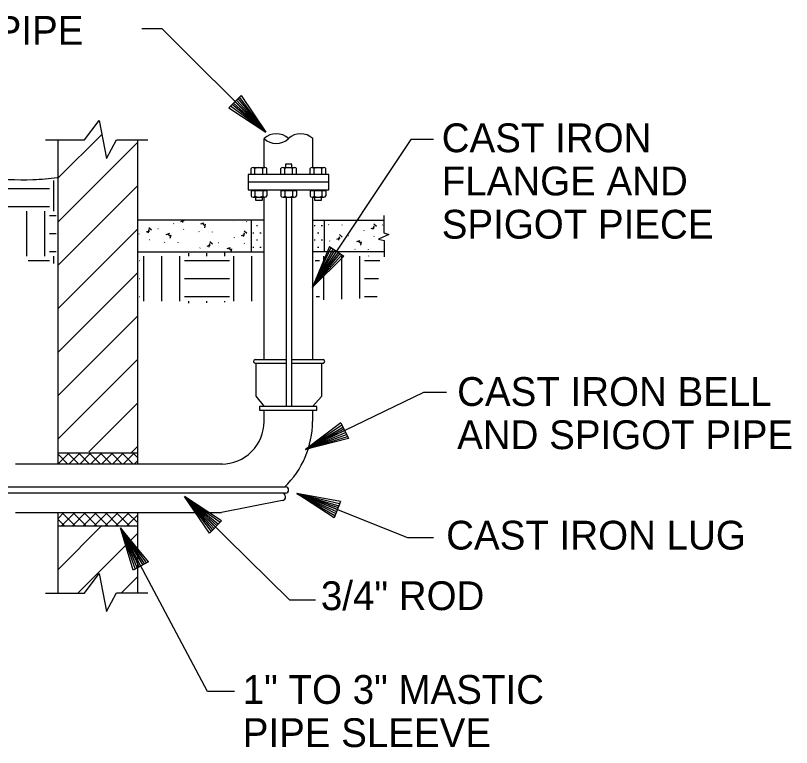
# Model space of a CAD drawing. Extents: x 9999.96 to 10005.26, y 9999.88 to 10002.38.
# Drawn here: x 10001.3058 to 10001.5752, y 10001.9706 to 10002.2247 of the extents above; entities that cross this region are included whole.
import ezdxf

# ---------------------------------------------------------------- set-up
doc = ezdxf.new("R2010")
doc.units = 0
doc.layers.add('Level 2', color=7, linetype='Continuous')

msp = doc.modelspace()

# ---------------------------------------------------------------- linework, layer by layer
at = {"layer": 'Level 2'}
for p, q in [((10001.379875, 10002.192729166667), (10001.384145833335, 10002.196989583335)), ((10001.392645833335, 10002.184208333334), (10001.382520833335, 10002.195375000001)), ((10001.392645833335, 10002.184208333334), (10001.383041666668, 10002.195906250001)), ((10001.392645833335, 10002.184208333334), (10001.383562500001, 10002.196416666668)), ((10001.384145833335, 10002.196989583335), (10001.392645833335, 10002.184208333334)), ((10001.379875, 10002.192729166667), (10001.392645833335, 10002.184208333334)), ((10001.392645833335, 10002.184208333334), (10001.380416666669, 10002.193270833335)), ((10001.392645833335, 10002.184208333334), (10001.381000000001, 10002.193885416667)), ((10001.392645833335, 10002.184208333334), (10001.381489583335, 10002.194343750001)), ((10001.381979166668, 10002.194843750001), (10001.392645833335, 10002.184208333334)), ((10001.320645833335, 10002.168333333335), (10001.335781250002, 10002.183468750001)), ((10001.392083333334, 10002.172010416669), (10001.392083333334, 10002.182)), ((10001.408885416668, 10002.182), (10001.408885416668, 10002.172010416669)), ((10001.320645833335, 10002.069031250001), (10001.320645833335, 10002.181541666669)), ((10001.320656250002, 10002.153250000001), (10001.348083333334, 10002.180687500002)), ((10001.348083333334, 10002.181541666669), (10001.348083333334, 10002.069031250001)), ((10001.387562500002, 10002.169677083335), (10001.387562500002, 10002.171583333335)), ((10001.388250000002, 10002.172010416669), (10001.392354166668, 10002.172010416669)), ((10001.388927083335, 10002.169677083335), (10001.388927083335, 10002.171583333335)), ((10001.391677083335, 10002.169677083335), (10001.391677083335, 10002.171583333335)), ((10001.393041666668, 10002.169677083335), (10001.393041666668, 10002.171572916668)), ((10001.397875, 10002.169677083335), (10001.397875, 10002.171583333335)), ((10001.3985625, 10002.172010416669), (10001.402666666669, 10002.172010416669)), ((10001.399239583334, 10002.169677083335), (10001.399239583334, 10002.171583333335)), ((10001.401989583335, 10002.169677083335), (10001.401989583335, 10002.171583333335)), ((10001.403354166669, 10002.169677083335), (10001.403354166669, 10002.171572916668)), ((10001.4080625, 10002.169677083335), (10001.4080625, 10002.171583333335)), ((10001.40875, 10002.172010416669), (10001.412854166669, 10002.172010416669)), ((10001.409427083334, 10002.169677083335), (10001.409427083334, 10002.171583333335)), ((10001.412177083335, 10002.169677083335), (10001.412177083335, 10002.171583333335)), ((10001.413541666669, 10002.169677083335), (10001.413541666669, 10002.171572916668)), ((10001.387562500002, 10002.169677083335), (10001.393041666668, 10002.169677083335)), ((10001.397875, 10002.169677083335), (10001.403354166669, 10002.169677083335)), ((10001.4080625, 10002.169677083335), (10001.413541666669, 10002.169677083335)), ((10001.319104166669, 10002.156843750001), (10001.319104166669, 10002.167500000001)), ((10001.320656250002, 10002.138166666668), (10001.348083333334, 10002.165604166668)), ((10001.414593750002, 10002.166833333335), (10001.386552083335, 10002.166833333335)), ((10001.301916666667, 10002.164656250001), (10001.317541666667, 10002.164656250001)), ((10001.387562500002, 10002.163989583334), (10001.393041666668, 10002.163989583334)), ((10001.387562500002, 10002.163989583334), (10001.387562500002, 10002.162083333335)), ((10001.388927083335, 10002.163989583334), (10001.388927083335, 10002.162083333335)), ((10001.391677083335, 10002.163989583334), (10001.391677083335, 10002.162083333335)), ((10001.393041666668, 10002.163989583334), (10001.393041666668, 10002.162093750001)), ((10001.397875, 10002.163989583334), (10001.403354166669, 10002.163989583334)), ((10001.397875, 10002.163989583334), (10001.397875, 10002.162083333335)), ((10001.399239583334, 10002.163989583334), (10001.399239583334, 10002.162083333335)), ((10001.401989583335, 10002.163989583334), (10001.401989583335, 10002.162083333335)), ((10001.403354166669, 10002.163989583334), (10001.403354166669, 10002.162093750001)), ((10001.4080625, 10002.163989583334), (10001.413541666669, 10002.163989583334)), ((10001.4080625, 10002.163989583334), (10001.4080625, 10002.162083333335)), ((10001.409427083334, 10002.163989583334), (10001.409427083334, 10002.162083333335)), ((10001.412177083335, 10002.163989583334), (10001.412177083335, 10002.162083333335)), ((10001.413541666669, 10002.163989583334), (10001.413541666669, 10002.162093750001)), ((10001.388250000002, 10002.161656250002), (10001.392354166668, 10002.161656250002)), ((10001.392083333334, 10002.105260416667), (10001.392083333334, 10002.161718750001)), ((10001.3985625, 10002.161656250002), (10001.402666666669, 10002.161656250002)), ((10001.39975, 10002.161656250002), (10001.39975, 10002.089010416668)), ((10001.401718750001, 10002.089010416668), (10001.401718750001, 10002.161656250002)), ((10001.40875, 10002.161656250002), (10001.412854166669, 10002.161656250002)), ((10001.408885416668, 10002.161656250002), (10001.408885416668, 10002.105260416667)), ((10001.301916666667, 10002.15840625), (10001.317541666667, 10002.15840625)), ((10001.309729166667, 10002.141218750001), (10001.309729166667, 10002.156843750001)), ((10001.315979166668, 10002.141218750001), (10001.315979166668, 10002.156843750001)), ((10001.317541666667, 10002.155281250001), (10001.319916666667, 10002.155281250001)), ((10001.392083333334, 10002.153645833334), (10001.348083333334, 10002.153645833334)), ((10001.360677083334, 10002.15246875), (10001.360697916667, 10002.152572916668)), ((10001.363156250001, 10002.153239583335), (10001.364354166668, 10002.153604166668)), ((10001.363916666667, 10002.153645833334), (10001.363729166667, 10002.152833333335)), ((10001.371177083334, 10002.152666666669), (10001.369979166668, 10002.152302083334)), ((10001.370614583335, 10002.152593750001), (10001.371520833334, 10002.15175)), ((10001.371468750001, 10002.151052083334), (10001.371750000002, 10002.152270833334)), ((10001.381510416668, 10002.153291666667), (10001.381437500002, 10002.153364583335)), ((10001.386052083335, 10002.153239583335), (10001.386031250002, 10002.153135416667)), ((10001.387645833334, 10002.153614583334), (10001.387645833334, 10002.142677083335)), ((10001.408885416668, 10002.153645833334), (10001.433614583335, 10002.153645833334)), ((10001.413, 10002.153645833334), (10001.413, 10002.142677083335)), ((10001.414572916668, 10002.15209375), (10001.4145, 10002.152156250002)), ((10001.416500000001, 10002.153479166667), (10001.416552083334, 10002.153697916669)), ((10001.431104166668, 10002.151489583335), (10001.430187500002, 10002.152343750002)), ((10001.320656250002, 10002.12309375), (10001.348083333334, 10002.150520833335)), ((10001.351208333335, 10002.149583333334), (10001.352395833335, 10002.149947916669)), ((10001.352041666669, 10002.150395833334), (10001.351760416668, 10002.149187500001)), ((10001.353020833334, 10002.150239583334), (10001.352114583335, 10002.151083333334)), ((10001.355187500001, 10002.150802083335), (10001.355312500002, 10002.150833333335)), ((10001.364197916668, 10002.150531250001), (10001.364104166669, 10002.150500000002)), ((10001.369552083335, 10002.149635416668), (10001.369479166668, 10002.149708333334)), ((10001.37409375, 10002.149583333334), (10001.374072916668, 10002.149489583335)), ((10001.386083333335, 10002.149031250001), (10001.385166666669, 10002.149885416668)), ((10001.389416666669, 10002.151843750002), (10001.389833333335, 10002.151843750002)), ((10001.391916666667, 10002.151843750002), (10001.3919375, 10002.151843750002)), ((10001.409427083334, 10002.151843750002), (10001.409833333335, 10002.151843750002)), ((10001.411916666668, 10002.151843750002), (10001.412343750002, 10002.151843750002)), ((10001.419125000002, 10002.152020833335), (10001.419104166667, 10002.151916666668)), ((10001.426822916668, 10002.150031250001), (10001.426843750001, 10002.150125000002)), ((10001.429260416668, 10002.150791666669), (10001.430458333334, 10002.151156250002)), ((10001.43015625, 10002.151614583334), (10001.429875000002, 10002.150395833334)), ((10001.433250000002, 10002.152010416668), (10001.433364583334, 10002.152041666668)), ((10001.317541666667, 10002.149031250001), (10001.319916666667, 10002.149031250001)), ((10001.348718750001, 10002.148822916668), (10001.348739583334, 10002.148916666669)), ((10001.352250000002, 10002.146875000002), (10001.352145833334, 10002.14684375)), ((10001.359218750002, 10002.149010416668), (10001.358020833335, 10002.148645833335)), ((10001.35865625, 10002.148937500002), (10001.359562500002, 10002.148083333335)), ((10001.359510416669, 10002.147395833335), (10001.359791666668, 10002.148614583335)), ((10001.381791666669, 10002.147593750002), (10001.381812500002, 10002.147697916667)), ((10001.384260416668, 10002.148354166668), (10001.385447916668, 10002.14871875)), ((10001.385114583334, 10002.149177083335), (10001.384833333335, 10002.147958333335)), ((10001.388166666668, 10002.149343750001), (10001.388583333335, 10002.149343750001)), ((10001.389416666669, 10002.14684375), (10001.389833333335, 10002.14684375)), ((10001.390666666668, 10002.149343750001), (10001.391083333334, 10002.149343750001)), ((10001.391916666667, 10002.14684375), (10001.391947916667, 10002.14684375)), ((10001.409427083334, 10002.14684375), (10001.409833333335, 10002.14684375)), ((10001.410666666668, 10002.149343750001), (10001.411083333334, 10002.149343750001)), ((10001.411916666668, 10002.14684375), (10001.412343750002, 10002.14684375)), ((10001.417312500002, 10002.147135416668), (10001.418500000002, 10002.147500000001)), ((10001.418187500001, 10002.147958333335), (10001.41790625, 10002.146739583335)), ((10001.419145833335, 10002.147822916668), (10001.418229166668, 10002.148677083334)), ((10001.421291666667, 10002.148354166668), (10001.421416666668, 10002.148385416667)), ((10001.430302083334, 10002.148083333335), (10001.430208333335, 10002.148052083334)), ((10001.35759375, 10002.145968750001), (10001.357520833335, 10002.146041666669)), ((10001.362135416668, 10002.145937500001), (10001.362114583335, 10002.145833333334)), ((10001.369822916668, 10002.143947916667), (10001.369854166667, 10002.144041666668)), ((10001.372302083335, 10002.144697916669), (10001.373500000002, 10002.145072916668)), ((10001.373156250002, 10002.145531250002), (10001.372875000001, 10002.1443125)), ((10001.374125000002, 10002.145375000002), (10001.373208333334, 10002.146218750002)), ((10001.37628125, 10002.145916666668), (10001.376406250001, 10002.145958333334)), ((10001.380322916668, 10002.144135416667), (10001.379125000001, 10002.143770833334)), ((10001.379750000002, 10002.144072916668), (10001.380666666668, 10002.143218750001)), ((10001.385302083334, 10002.14565625), (10001.385197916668, 10002.145625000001)), ((10001.388166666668, 10002.144343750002), (10001.388583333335, 10002.144343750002)), ((10001.390666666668, 10002.144343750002), (10001.391083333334, 10002.144343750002)), ((10001.414770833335, 10002.144583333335), (10001.408947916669, 10002.130375)), ((10001.408947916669, 10002.130375), (10001.415406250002, 10002.144156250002)), ((10001.410666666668, 10002.144343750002), (10001.411083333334, 10002.144343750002)), ((10001.414770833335, 10002.144583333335), (10001.41978125, 10002.141239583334)), ((10001.414864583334, 10002.146375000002), (10001.414885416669, 10002.146479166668)), ((10001.418354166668, 10002.144437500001), (10001.41825, 10002.144406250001)), ((10001.425322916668, 10002.146562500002), (10001.424125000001, 10002.146197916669)), ((10001.424770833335, 10002.14653125), (10001.425687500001, 10002.145677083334)), ((10001.425656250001, 10002.144958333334), (10001.425937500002, 10002.146166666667)), ((10001.317541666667, 10002.14278125), (10001.319916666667, 10002.14278125)), ((10001.348083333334, 10002.142666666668), (10001.392083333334, 10002.142666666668)), ((10001.365979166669, 10002.141218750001), (10001.365979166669, 10002.142187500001)), ((10001.372229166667, 10002.141218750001), (10001.372229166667, 10002.142239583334)), ((10001.378479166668, 10002.141218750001), (10001.378479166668, 10002.142291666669)), ((10001.380635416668, 10002.14259375), (10001.380895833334, 10002.143739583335)), ((10001.433614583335, 10002.142666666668), (10001.408885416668, 10002.142666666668)), ((10001.408947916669, 10002.130375), (10001.416125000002, 10002.143708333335)), ((10001.408947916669, 10002.130375), (10001.416666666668, 10002.143322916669)), ((10001.417260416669, 10002.1429375), (10001.408947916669, 10002.130375)), ((10001.408947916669, 10002.130375), (10001.417885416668, 10002.142510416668)), ((10001.408947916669, 10002.130375), (10001.418510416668, 10002.142114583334)), ((10001.408947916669, 10002.130375), (10001.419104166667, 10002.141697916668)), ((10001.423718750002, 10002.143562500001), (10001.423645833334, 10002.143635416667)), ((10001.42828125, 10002.143489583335), (10001.428260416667, 10002.143385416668)), ((10001.428479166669, 10002.141218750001), (10001.428479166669, 10002.141322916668)), ((10001.310208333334, 10002.139656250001), (10001.317541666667, 10002.139656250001)), ((10001.319104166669, 10002.138666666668), (10001.319104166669, 10002.141218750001)), ((10001.348708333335, 10002.139656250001), (10001.348791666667, 10002.139656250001)), ((10001.350354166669, 10002.125593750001), (10001.350354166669, 10002.141218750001)), ((10001.356604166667, 10002.125593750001), (10001.356604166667, 10002.141218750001)), ((10001.362854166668, 10002.125593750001), (10001.362854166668, 10002.141218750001)), ((10001.364416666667, 10002.139656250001), (10001.380041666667, 10002.139656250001)), ((10001.381604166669, 10002.125593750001), (10001.381604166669, 10002.141218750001)), ((10001.387854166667, 10002.125593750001), (10001.387854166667, 10002.141218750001)), ((10001.41978125, 10002.141239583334), (10001.408947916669, 10002.130375)), ((10001.409802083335, 10002.139656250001), (10001.411291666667, 10002.139656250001)), ((10001.412854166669, 10002.126000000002), (10001.412854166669, 10002.141218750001)), ((10001.419104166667, 10002.126229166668), (10001.419104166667, 10002.141218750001)), ((10001.425364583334, 10002.126458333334), (10001.425364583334, 10002.141218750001)), ((10001.426916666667, 10002.139656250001), (10001.432281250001, 10002.139656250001)), ((10001.320656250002, 10002.108010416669), (10001.348083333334, 10002.135437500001)), ((10001.348708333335, 10002.133406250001), (10001.348791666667, 10002.133406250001)), ((10001.364416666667, 10002.133406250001), (10001.380041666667, 10002.133406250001)), ((10001.409958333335, 10002.133406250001), (10001.411291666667, 10002.133406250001)), ((10001.426916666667, 10002.133406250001), (10001.431791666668, 10002.133406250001)), ((10001.348708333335, 10002.12715625), (10001.348791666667, 10002.12715625)), ((10001.364416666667, 10002.12715625), (10001.380041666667, 10002.12715625)), ((10001.365979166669, 10002.124833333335), (10001.365979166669, 10002.125593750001)), ((10001.372229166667, 10002.125000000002), (10001.372229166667, 10002.125593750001)), ((10001.378479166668, 10002.125166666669), (10001.378479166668, 10002.125593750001)), ((10001.410114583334, 10002.12715625), (10001.411291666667, 10002.12715625)), ((10001.426916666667, 10002.12715625), (10001.431291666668, 10002.12715625)), ((10001.320666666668, 10002.092927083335), (10001.348083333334, 10002.12034375)), ((10001.320666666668, 10002.077843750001), (10001.34809375, 10002.105260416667)), ((10001.388947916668, 10002.105260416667), (10001.39975, 10002.105260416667)), ((10001.388947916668, 10002.104083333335), (10001.39975, 10002.104083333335)), ((10001.389177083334, 10002.104083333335), (10001.389177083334, 10002.092604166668)), ((10001.401718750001, 10002.105260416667), (10001.412541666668, 10002.105260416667)), ((10001.401718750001, 10002.104083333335), (10001.412541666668, 10002.104083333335)), ((10001.412177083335, 10002.092645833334), (10001.412177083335, 10002.104083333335)), ((10001.331208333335, 10002.073291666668), (10001.34809375, 10002.090177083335)), ((10001.389177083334, 10002.092604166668), (10001.392083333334, 10002.089010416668)), ((10001.40890625, 10002.089010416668), (10001.412177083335, 10002.092645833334)), ((10001.392083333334, 10002.083760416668), (10001.392083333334, 10002.087677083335)), ((10001.408885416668, 10002.087677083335), (10001.408885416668, 10002.083760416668)), ((10001.418739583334, 10002.0833125), (10001.406479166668, 10002.074072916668)), ((10001.406479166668, 10002.074072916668), (10001.419072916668, 10002.082625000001)), ((10001.418739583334, 10002.0833125), (10001.421343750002, 10002.077885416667)), ((10001.406479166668, 10002.074072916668), (10001.419458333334, 10002.081875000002)), ((10001.406479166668, 10002.074072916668), (10001.419729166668, 10002.081260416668)), ((10001.420041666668, 10002.080635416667), (10001.406479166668, 10002.074072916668)), ((10001.406479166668, 10002.074072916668), (10001.420364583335, 10002.079947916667)), ((10001.406479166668, 10002.074072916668), (10001.420697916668, 10002.079281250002)), ((10001.406479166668, 10002.074072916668), (10001.421000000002, 10002.078625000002)), ((10001.421343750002, 10002.077885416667), (10001.406479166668, 10002.074072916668)), ((10001.346000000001, 10002.073000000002), (10001.34809375, 10002.075093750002)), ((10001.320645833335, 10002.069135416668), (10001.324322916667, 10002.072802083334)), ((10001.32396875, 10002.069031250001), (10001.320656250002, 10002.072333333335)), ((10001.348083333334, 10002.072802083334), (10001.320666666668, 10002.072802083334)), ((10001.327739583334, 10002.069031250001), (10001.323958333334, 10002.072802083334)), ((10001.3243125, 10002.069031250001), (10001.328093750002, 10002.072802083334)), ((10001.331510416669, 10002.069031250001), (10001.327729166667, 10002.072802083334)), ((10001.328083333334, 10002.069031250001), (10001.331864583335, 10002.072802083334)), ((10001.335281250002, 10002.069031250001), (10001.331510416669, 10002.072802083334)), ((10001.331864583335, 10002.069031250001), (10001.335635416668, 10002.072802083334)), ((10001.339052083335, 10002.069031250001), (10001.335281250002, 10002.072802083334)), ((10001.335635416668, 10002.069031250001), (10001.339406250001, 10002.072802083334)), ((10001.342822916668, 10002.069031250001), (10001.339052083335, 10002.072802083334)), ((10001.339406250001, 10002.069031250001), (10001.343177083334, 10002.072802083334)), ((10001.34659375, 10002.069031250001), (10001.342822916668, 10002.072802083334)), ((10001.343177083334, 10002.069031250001), (10001.346947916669, 10002.072802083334)), ((10001.348083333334, 10002.071302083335), (10001.34659375, 10002.072802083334)), ((10001.377697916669, 10002.069031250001), (10001.305802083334, 10002.069031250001)), ((10001.346947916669, 10002.069031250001), (10001.348083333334, 10002.070177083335)), ((10001.225822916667, 10002.0610625), (10001.399572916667, 10002.0610625)), ((10001.399572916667, 10002.058968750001), (10001.225927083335, 10002.058968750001)), ((10001.375239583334, 10002.047218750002), (10001.364500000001, 10002.057781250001)), ((10001.373083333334, 10002.045062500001), (10001.364500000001, 10002.057781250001)), ((10001.377322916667, 10002.04934375), (10001.364500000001, 10002.057781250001)), ((10001.364500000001, 10002.057781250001), (10001.374187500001, 10002.046145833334)), ((10001.364500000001, 10002.057781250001), (10001.376208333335, 10002.0481875)), ((10001.364500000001, 10002.057781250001), (10001.373666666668, 10002.045635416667)), ((10001.364500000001, 10002.057781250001), (10001.374697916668, 10002.046687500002)), ((10001.364500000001, 10002.057781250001), (10001.375729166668, 10002.047718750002)), ((10001.364500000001, 10002.057781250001), (10001.376791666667, 10002.048802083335)), ((10001.417520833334, 10002.053229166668), (10001.403510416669, 10002.058770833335)), ((10001.416375, 10002.050406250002), (10001.403510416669, 10002.058770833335)), ((10001.418614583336, 10002.056), (10001.403510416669, 10002.058770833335)), ((10001.403510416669, 10002.058770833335), (10001.416968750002, 10002.051833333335)), ((10001.403510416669, 10002.058770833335), (10001.418031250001, 10002.054500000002)), ((10001.403510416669, 10002.058770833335), (10001.416687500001, 10002.051166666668)), ((10001.403510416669, 10002.058770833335), (10001.417229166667, 10002.052531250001)), ((10001.403510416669, 10002.058770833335), (10001.417770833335, 10002.053885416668)), ((10001.403510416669, 10002.058770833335), (10001.418322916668, 10002.055291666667)), ((10001.398385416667, 10002.0563125), (10001.377354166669, 10002.052218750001)), ((10001.418614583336, 10002.056), (10001.416375, 10002.050406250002)), ((10001.305802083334, 10002.052218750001), (10001.377354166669, 10002.052218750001)), ((10001.320645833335, 10002.024208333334), (10001.320645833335, 10002.052104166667)), ((10001.320656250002, 10002.050281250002), (10001.322479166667, 10002.052104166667)), ((10001.322739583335, 10002.047625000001), (10001.320656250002, 10002.049708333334)), ((10001.321770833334, 10002.047625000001), (10001.326250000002, 10002.052104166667)), ((10001.326510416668, 10002.047625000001), (10001.322031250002, 10002.052104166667)), ((10001.325541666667, 10002.047625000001), (10001.330020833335, 10002.052104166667)), ((10001.33028125, 10002.047625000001), (10001.325802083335, 10002.052104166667)), ((10001.329312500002, 10002.047625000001), (10001.333791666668, 10002.052104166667)), ((10001.334052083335, 10002.047625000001), (10001.329572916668, 10002.052104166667)), ((10001.333083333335, 10002.047625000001), (10001.3375625, 10002.052104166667)), ((10001.337822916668, 10002.047625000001), (10001.33334375, 10002.052104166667)), ((10001.336854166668, 10002.047625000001), (10001.341333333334, 10002.052104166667)), ((10001.341593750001, 10002.047625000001), (10001.337114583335, 10002.052104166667)), ((10001.340625, 10002.047625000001), (10001.345104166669, 10002.052104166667)), ((10001.345364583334, 10002.047625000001), (10001.340885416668, 10002.052104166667)), ((10001.344395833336, 10002.047625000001), (10001.348083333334, 10002.051312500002)), ((10001.348083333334, 10002.048677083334), (10001.344656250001, 10002.052104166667)), ((10001.348083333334, 10002.052104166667), (10001.348083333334, 10002.024208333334)), ((10001.320656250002, 10002.032572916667), (10001.335791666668, 10002.047718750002)), ((10001.320666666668, 10002.047625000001), (10001.348083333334, 10002.047625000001)), ((10001.377322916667, 10002.04934375), (10001.373083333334, 10002.045062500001)), ((10001.327479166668, 10002.024312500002), (10001.34809375, 10002.044927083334)), ((10001.349343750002, 10002.033614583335), (10001.342270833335, 10002.046916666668)), ((10001.346645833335, 10002.032208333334), (10001.342270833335, 10002.046916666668)), ((10001.351979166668, 10002.035020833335), (10001.342270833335, 10002.046916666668)), ((10001.342270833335, 10002.046916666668), (10001.348020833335, 10002.032916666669)), ((10001.342270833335, 10002.046916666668), (10001.350562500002, 10002.03425)), ((10001.342270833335, 10002.046916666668), (10001.347375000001, 10002.032583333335)), ((10001.342270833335, 10002.046916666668), (10001.348677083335, 10002.033270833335)), ((10001.342270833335, 10002.046916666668), (10001.34996875, 10002.033958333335)), ((10001.342270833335, 10002.046916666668), (10001.351302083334, 10002.034666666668)), ((10001.351979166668, 10002.035020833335), (10001.346645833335, 10002.032208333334)), ((10001.342541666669, 10002.024291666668), (10001.348083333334, 10002.029833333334))]:
    msp.add_line(p, q, dxfattribs=at)
for points in [[(10001.349677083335, 10002.220260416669), (10001.35659375, 10002.220260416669), (10001.392645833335, 10002.184208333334)], [(10001.316208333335, 10002.181520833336), (10001.329687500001, 10002.181520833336), (10001.334864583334, 10002.188291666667), (10001.337375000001, 10002.175125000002), (10001.340885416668, 10002.181593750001), (10001.351697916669, 10002.181593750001)], [(10001.450927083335, 10002.181739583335), (10001.443020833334, 10002.181739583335), (10001.408947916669, 10002.130375)], [(10001.40175, 10002.172020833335), (10001.40175, 10002.173166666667), (10001.399489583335, 10002.173166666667), (10001.399489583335, 10002.172020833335)], [(10001.3914375, 10002.161645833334), (10001.3914375, 10002.160500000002), (10001.389177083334, 10002.160500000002), (10001.389177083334, 10002.161645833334)], [(10001.411937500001, 10002.161645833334), (10001.411937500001, 10002.160500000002), (10001.409677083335, 10002.160500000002), (10001.409677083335, 10002.161645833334)], [(10001.433645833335, 10002.15534375), (10001.433645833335, 10002.149281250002), (10001.435343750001, 10002.148708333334), (10001.431864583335, 10002.147093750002), (10001.433729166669, 10002.146614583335), (10001.433729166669, 10002.140958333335)], [(10001.455364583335, 10002.093833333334), (10001.44746875, 10002.093833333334), (10001.406479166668, 10002.074072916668)], [(10001.409927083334, 10002.021729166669), (10001.401041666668, 10002.021729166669), (10001.364500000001, 10002.057781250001)], [(10001.450927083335, 10002.043458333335), (10001.44203125, 10002.043458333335), (10001.403510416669, 10002.058770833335)], [(10001.381781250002, 10001.990114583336), (10001.372395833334, 10001.990114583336), (10001.342270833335, 10002.046916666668)], [(10001.316208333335, 10002.02421875), (10001.329687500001, 10002.02421875), (10001.334864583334, 10002.030989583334), (10001.337375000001, 10002.017822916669), (10001.340885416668, 10002.024291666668), (10001.351697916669, 10002.024291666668)]]:
    msp.add_lwpolyline(points, dxfattribs=at)
for points in [[(10001.386510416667, 10002.169562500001), (10001.386510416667, 10002.1641875), (10001.414593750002, 10002.1641875), (10001.414593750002, 10002.169562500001)], [(10001.390510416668, 10002.089010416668), (10001.390510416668, 10002.087677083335), (10001.410385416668, 10002.087677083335), (10001.410385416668, 10002.089010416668)]]:
    msp.add_lwpolyline(points, close=True, dxfattribs=at)
for centre, radius, start, end in [((10001.396304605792, 10002.186368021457), 0.006074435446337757, 225.97880833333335, 314.0225027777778), ((10001.396304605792, 10002.177631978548), 0.0060744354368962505, 45.97749722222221, 134.02119166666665), ((10001.404747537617, 10002.177631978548), 0.006074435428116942, 45.97880833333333, 134.0225027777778), ((10001.388244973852, 10002.171235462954), 0.0007663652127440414, 27.88770000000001, 152.03418611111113), ((10001.390299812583, 10002.16946942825), 0.0025319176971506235, 57.006158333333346, 122.94297500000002), ((10001.392355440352, 10002.171229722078), 0.000766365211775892, 26.78268611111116, 151.83909722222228), ((10001.398557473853, 10002.171235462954), 0.0007663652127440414, 27.88770000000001, 152.03418611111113), ((10001.400612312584, 10002.16946942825), 0.0025319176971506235, 57.006158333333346, 122.94297500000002), ((10001.402667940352, 10002.171229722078), 0.000766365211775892, 26.78268611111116, 151.83909722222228), ((10001.408744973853, 10002.171235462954), 0.0007663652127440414, 27.88770000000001, 152.03418611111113), ((10001.410799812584, 10002.16946942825), 0.0025319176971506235, 57.006158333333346, 122.94297500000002), ((10001.412855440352, 10002.171229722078), 0.000766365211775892, 26.78268611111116, 151.83909722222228), ((10001.388244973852, 10002.162431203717), 0.0007663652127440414, 207.9658138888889, 332.1123), ((10001.390299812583, 10002.164197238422), 0.0025319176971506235, 237.05702500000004, 302.9938416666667), ((10001.392355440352, 10002.162436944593), 0.000766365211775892, 208.16090277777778, 333.2173138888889), ((10001.398557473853, 10002.162431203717), 0.0007663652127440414, 207.9658138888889, 332.1123), ((10001.400612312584, 10002.164197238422), 0.0025319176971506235, 237.05702500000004, 302.9938416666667), ((10001.402667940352, 10002.162436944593), 0.000766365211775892, 208.16090277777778, 333.2173138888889), ((10001.408744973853, 10002.162431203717), 0.0007663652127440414, 207.9658138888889, 332.1123), ((10001.410799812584, 10002.164197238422), 0.0025319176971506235, 237.05702500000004, 302.9938416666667), ((10001.412855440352, 10002.162436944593), 0.000766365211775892, 208.16090277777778, 333.2173138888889), ((10001.388947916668, 10002.104671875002), 0.0005885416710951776, 90, 270), ((10001.412541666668, 10002.104671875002), 0.0005885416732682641, 270, 90), ((10001.37734994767, 10002.083759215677), 0.014732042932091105, 269.9846972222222, 359.9999972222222), ((10001.377348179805, 10002.08375941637), 0.03153853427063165, 313.9738583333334, 0.0018166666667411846), ((10001.399572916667, 10002.060015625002), 0.0010468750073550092, 270, 90), ((10001.39820658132, 10002.057635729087), 0.0013330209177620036, 277.6969277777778, 91.68871944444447)]:
    msp.add_arc(centre, radius, start, end, dxfattribs=at)
msp.add_spline([(10001.320291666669, 10002.168354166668), (10001.311843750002, 10002.167666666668), (10001.294760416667, 10002.168177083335), (10001.281468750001, 10002.168354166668), (10001.263520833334, 10002.167489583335), (10001.244197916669, 10002.167145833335), (10001.23021875, 10002.167666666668)], degree=3, dxfattribs=at)

# ---------------------------------------------------------------- texts
for s, p in [('STEEL PIPE', (10001.252802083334, 10002.214583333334)), ('CAST IRON', (10001.453760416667, 10002.177281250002)), ('FLANGE AND', (10001.453760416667, 10002.16228125)), ('SPIGOT PIECE', (10001.453760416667, 10002.147281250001)), ('CAST IRON BELL', (10001.459114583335, 10002.089197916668)), ('AND SPIGOT PIPE', (10001.459114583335, 10002.074197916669)), ('CAST IRON LUG', (10001.455312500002, 10002.039333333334)), ('3/4" ROD', (10001.411802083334, 10002.018312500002)), ('1" TO 3" MASTIC', (10001.384666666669, 10001.985770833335)), ('PIPE SLEEVE', (10001.384666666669, 10001.970770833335))]:
    msp.add_text(s, height=0.010000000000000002, dxfattribs=at).set_placement(p)

doc.saveas('drawing.dxf')
